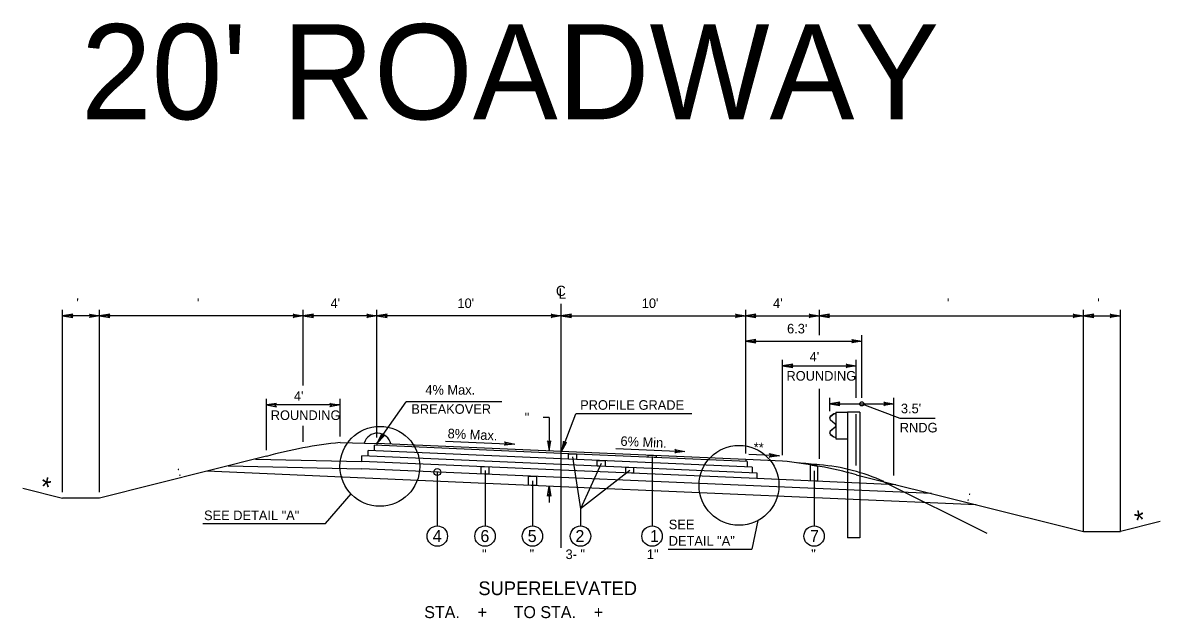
# Model space of a CAD drawing. Extents: x -540 to 1231, y -564 to 421.
# Drawn here: x 503.3 to 669.6, y -129.2 to -42.2 of the extents above; entities that cross this region are included whole.
import ezdxf

# ---------------------------------------------------------------- set-up
doc = ezdxf.new("R2010")
doc.units = 0
doc.layers.add('1', color=7, linetype='Continuous')
doc.layers.add('Des_ Drain_ Ftrs', color=7, linetype='Continuous')

msp = doc.modelspace()

# ---------------------------------------------------------------- linework, layer by layer
at = {"layer": '1'}
for p, q in [((509.17, -110.78), (509.17, -84.16)), ((514.55, -110.78), (514.55, -84.16)), ((544.33, -95.22), (544.33, -84.16)), ((555.1, -102.79), (555.1, -84.16)), ((582.04, -118.94), (582.04, -83.28)), ((608.98, -105.14), (608.98, -84.16)), ((619.76, -87.87), (619.76, -84.16)), ((658.35, -116.57), (658.35, -84.16)), ((663.74, -116.57), (663.74, -84.16)), ((514.55, -85.04), (509.17, -85.04)), ((544.33, -85.04), (514.55, -85.04)), ((555.1, -85.04), (544.33, -85.04)), ((582.04, -85.04), (555.1, -85.04)), ((582.04, -85.04), (608.98, -85.04)), ((608.98, -85.04), (619.76, -85.04)), ((619.76, -85.04), (658.35, -85.04)), ((658.35, -85.04), (663.74, -85.04)), ((625.95, -97.02), (625.95, -87.87)), ((608.98, -88.75), (625.95, -88.75)), ((614.37, -105.38), (614.37, -91.44)), ((614.37, -92.32), (625.15, -92.32)), ((625.15, -97.02), (625.15, -91.44)), ((619.76, -105.93), (619.76, -95.72)), ((538.94, -104.68), (538.94, -97.18)), ((549.71, -98.06), (538.94, -98.06)), ((549.71, -102.67), (549.71, -97.18)), ((555.1, -103.67), (559.38, -97.58)), ((573.33, -97.58), (559.38, -97.58)), ((621.26, -98.97), (621.26, -97.02)), ((621.26, -97.9), (630.65, -97.9)), ((625.95, -97.9), (631.51, -99.97)), ((630.65, -108.38), (630.65, -97.02)), ((582.05, -104.85), (584.17, -99.34)), ((601.09, -99.34), (584.17, -99.34)), ((621.86, -99.37), (621.34, -99.76)), ((621.87, -99.4), (621.36, -99.78)), ((622.17, -99.31), (621.86, -99.37)), ((622.17, -99.35), (621.87, -99.4)), ((622.17, -99.09), (622.17, -103.02)), ((622.17, -99.09), (623.86, -99.09)), ((623.86, -99.09), (623.86, -117.48)), ((625.68, -99.09), (623.86, -99.09)), ((625.15, -106.9), (625.15, -99.4)), ((625.68, -99.09), (625.68, -117.48)), ((544.33, -103.45), (544.33, -101.13)), ((580.26, -99.89), (579.38, -99.89)), ((580.26, -99.89), (580.26, -104.77)), ((621.33, -100.19), (622.06, -100.83)), ((622.06, -101.28), (621.33, -101.91)), ((621.35, -100.17), (622.08, -100.8)), ((622.08, -101.3), (621.35, -101.94)), ((622.14, -101.01), (622.14, -101.09)), ((622.17, -101.01), (622.17, -101.09)), ((631.51, -99.97), (636.67, -99.97)), ((621.34, -102.35), (621.86, -102.73)), ((621.36, -102.32), (621.87, -102.71)), ((621.86, -102.73), (622.17, -102.79)), ((621.87, -102.71), (622.17, -102.76)), ((622.17, -103.02), (623.86, -103.02)), ((549.71, -103.55), (555.1, -103.67)), ((582.04, -105.95), (553.83, -104.72)), ((553.83, -105.53), (553.83, -104.72)), ((582.04, -105.14), (554.76, -103.95)), ((554.76, -104.76), (554.76, -103.95)), ((582.04, -104.84), (555.1, -103.67)), ((555.1, -103.67), (555.1, -103.97)), ((565.12, -103.33), (575.23, -103.77)), ((589.99, -104.42), (600.11, -104.86)), ((538.94, -105.56), (514.55, -111.66)), ((537.34, -105.96), (552.91, -106.3)), ((582.04, -106.76), (552.91, -105.49)), ((552.91, -106.3), (552.91, -105.49)), ((552.91, -105.49), (552.91, -105.49)), ((582.04, -107.57), (552.91, -106.3)), ((608.99, -106.02), (582.04, -104.84)), ((609.22, -106.33), (582.04, -105.14)), ((609.93, -107.17), (582.04, -105.95)), ((583.68, -105.62), (584.84, -113.25)), ((595.3, -105.59), (595.3, -115.73)), ((614.37, -106.26), (608.99, -106.02)), ((608.99, -106.02), (608.99, -106.32)), ((609.22, -106.33), (609.22, -107.14)), ((613.93, -105.48), (609.43, -105.29)), ((582.04, -110), (530.24, -107.74)), ((533.37, -106.95), (552.91, -107.38)), ((582.04, -108.65), (552.91, -107.38)), ((563.92, -107.86), (563.92, -115.73)), ((570.89, -107.62), (570.89, -115.73)), ((610.63, -108.01), (582.04, -106.76)), ((610.63, -108.82), (582.04, -107.57)), ((587.85, -106.6), (584.84, -113.25)), ((592.03, -107.62), (584.84, -113.25)), ((609.93, -107.17), (609.93, -107.98)), ((610.63, -108.01), (610.63, -108.82)), ((610.64, -108.01), (610.63, -108.01)), ((618.98, -107.68), (618.98, -115.73)), ((621.26, -107.03), (621.26, -107.03)), ((577.82, -109.13), (577.82, -115.73)), ((608.99, -109.83), (582.04, -108.65)), ((630.9, -109.71), (610.63, -108.82)), ((625.15, -108.27), (658.35, -116.57)), ((629.15, -109.27), (644.2, -116.79)), ((503.34, -110.2), (509.17, -111.66)), ((547.57, -115.39), (551.31, -111.07)), ((580.26, -109.92), (580.26, -112.29)), ((642.67, -112.65), (582.04, -110)), ((636.13, -111.01), (608.99, -109.83)), ((514.55, -111.66), (509.17, -111.66)), ((584.84, -113.25), (584.84, -115.73)), ((529.64, -115.39), (547.57, -115.39)), ((610.78, -114.94), (609.89, -119.12)), ((669.56, -115.11), (663.74, -116.57)), ((625.68, -117.48), (623.86, -117.48)), ((658.35, -116.57), (663.74, -116.57)), ((597.66, -119.12), (609.89, -119.12))]:
    msp.add_line(p, q, dxfattribs=at)
for points in [[(583.11, -105.19), (584.25, -105.24), (584.25, -106.05), (583.11, -106)], [(587.28, -106.18), (588.43, -106.23), (588.43, -107.04), (587.28, -106.99)], [(594.73, -105.4), (595.88, -105.45), (595.88, -105.75), (594.73, -105.7)], [(570.31, -107.06), (571.46, -107.11), (571.46, -108.19), (570.31, -108.14)], [(591.46, -107.17), (592.6, -107.22), (592.6, -108.03), (591.46, -107.98)], [(618.46, -106.81), (619.5, -106.99), (619.5, -109.21), (618.46, -109.16)], [(577.25, -108.44), (578.39, -108.49), (578.39, -109.84), (577.25, -109.79)]]:
    msp.add_lwpolyline(points, close=True, dxfattribs=at)
for centre, radius in [((625.95, -97.9), 0.3), ((555.52, -107.03), 5.84), ((608.01, -109.8), 5.84), ((563.92, -107.86), 0.5), ((563.92, -117.22), 1.49), ((570.89, -117.22), 1.49), ((577.82, -117.22), 1.49), ((584.84, -117.22), 1.49), ((595.3, -117.22), 1.49), ((618.98, -117.22), 1.49)]:
    msp.add_circle(centre, radius, dxfattribs=at)
for centre, radius, start, end in [((621.51, -99.98), 0.278, 126.9799, 229.021), ((621.51, -99.98), 0.249, 126.9799, 229.021), ((621.9, -101.01), 0.249, 0, 49.0365), ((621.9, -101.09), 0.249, 310.9635, 0), ((621.9, -101.01), 0.278, 0, 49.0365), ((621.9, -101.09), 0.278, 310.9635, 0), ((555.17, -104.18), 2, 12.2852, 163.8849), ((621.51, -102.12), 0.278, 130.979, 233.0201), ((621.51, -102.12), 0.249, 130.979, 233.0201), ((556.61, -170.39), 67.19, 95.8901, 105.2487), ((607.49, -173.09), 67.19, 74.7593, 84.1179), ((608.94, -207.48), 101.24, 83.8633, 85.6775), ((617.64, -134.1), 27.37, 65.1374, 85.5513)]:
    msp.add_arc(centre, radius, start, end, dxfattribs=at)
at = {"layer": 'Des_ Drain_ Ftrs'}
for points in [[(509.17, -85.04), (510.65, -85.29), (510.36, -85.04), (510.65, -84.8)], [(514.55, -85.04), (513.07, -85.29), (513.36, -85.04), (513.07, -84.8)], [(514.55, -85.04), (516.04, -85.29), (515.75, -85.04), (516.04, -84.8)], [(544.33, -85.04), (542.84, -85.29), (543.13, -85.04), (542.84, -84.8)], [(544.33, -85.04), (545.81, -85.29), (545.52, -85.04), (545.81, -84.8)], [(555.1, -85.04), (553.61, -85.29), (553.91, -85.04), (553.61, -84.8)], [(555.1, -85.04), (556.59, -85.29), (556.3, -85.04), (556.59, -84.8)], [(582.04, -85.04), (580.55, -85.29), (580.85, -85.04), (580.55, -84.8)], [(582.04, -85.04), (583.53, -85.29), (583.24, -85.04), (583.53, -84.8)], [(608.98, -85.04), (607.5, -85.29), (607.79, -85.04), (607.5, -84.8)], [(608.98, -85.04), (610.47, -85.29), (610.18, -85.04), (610.47, -84.8)], [(619.76, -85.04), (618.27, -85.29), (618.57, -85.04), (618.27, -84.8)], [(619.76, -85.04), (621.25, -85.29), (620.95, -85.04), (621.25, -84.8)], [(658.35, -85.04), (656.86, -85.29), (657.15, -85.04), (656.86, -84.8)], [(658.35, -85.04), (659.84, -85.29), (659.54, -85.04), (659.84, -84.8)], [(663.74, -85.04), (662.25, -85.29), (662.54, -85.04), (662.25, -84.8)], [(608.98, -88.75), (610.47, -88.99), (610.17, -88.75), (610.47, -88.5)], [(625.95, -88.75), (624.47, -88.99), (624.76, -88.75), (624.47, -88.5)], [(614.37, -92.32), (615.86, -92.57), (615.57, -92.32), (615.86, -92.07)], [(625.15, -92.32), (623.66, -92.57), (623.96, -92.32), (623.66, -92.07)], [(538.94, -98.06), (540.43, -98.31), (540.13, -98.06), (540.43, -97.82)], [(549.71, -98.06), (548.23, -98.31), (548.52, -98.06), (548.23, -97.82)], [(621.26, -97.9), (622.75, -98.15), (622.45, -97.9), (622.75, -97.65)], [(630.65, -97.9), (629.16, -98.15), (629.45, -97.9), (629.16, -97.65)], [(555.1, -103.67), (556.15, -102.59), (555.78, -102.69), (555.75, -102.31)], [(575.23, -103.77), (573.74, -103.95), (574.04, -103.72), (573.76, -103.46)], [(580.26, -104.77), (580.51, -103.28), (580.26, -103.57), (580.02, -103.28)], [(582.05, -104.85), (582.82, -103.55), (582.48, -103.74), (582.35, -103.37)], [(600.11, -104.86), (598.61, -105.05), (598.91, -104.81), (598.63, -104.55)], [(613.93, -105.48), (612.43, -105.67), (612.73, -105.43), (612.45, -105.17)], [(580.26, -109.92), (580.51, -111.41), (580.26, -111.11), (580.02, -111.41)]]:
    msp.add_lwpolyline(points, close=True, dxfattribs=at)

# ---------------------------------------------------------------- texts
at = {"layer": '1'}
for s, height, p in [("20' ROADWAY", 13.8979, (511.85, -56.3)), (" '", 1.4, (510.66, -83.89)), ("  '", 1.4, (527.74, -83.89)), ("4'", 1.4, (548.32, -83.89)), ("10'", 1.4, (566.86, -83.89)), ("10'", 1.4, (593.8, -83.89)), ("4'", 1.4, (612.98, -83.89)), ("  '", 1.4, (637.36, -83.89)), (" '", 1.4, (659.85, -83.89)), ("6.3'", 1.4, (615.03, -87.6)), ("4'", 1.4, (618.33, -91.7)), ('ROUNDING', 1.4, (614.94, -94.5)), ("4'", 1.4, (542.97, -97.45)), ('4% Max.', 1.4, (562.17, -96.55)), ('BREAKOVER', 1.4, (560.12, -99.35)), ('PROFILE GRADE', 1.4, (584.79, -98.76)), ("3.5'", 1.4, (631.67, -99.27)), ('ROUNDING', 1.4, (539.58, -100.25)), ('RNDG', 1.4, (631.5, -102.07)), ('SEE DETAIL "A"', 1.4, (529.83, -114.89)), ('4', 1.75, (563.25, -118.09)), ('6', 1.75, (570.22, -118.09)), ('5', 1.75, (577.13, -118.09)), ('2', 1.75, (584.1, -118.09)), ('1', 1.75, (595, -118.09)), ('SEE', 1.4, (597.74, -116.22)), ('7', 1.75, (618.39, -118.09)), ('DETAIL "A"', 1.4, (597.74, -118.62)), (' "', 1.4, (569.94, -120.58)), (' "', 1.4, (576.88, -120.58)), ('3- "', 1.4, (582.66, -120.58)), ('1"', 1.4, (594.54, -120.58)), (' "', 1.4, (618.04, -120.58)), ('SUPERELEVATED', 2, (569.92, -125.85)), ('STA.    +      TO STA.    +     ', 1.75, (562.01, -129.21))]:
    msp.add_text(s, height=height, dxfattribs=at).set_placement(p)
for s, height, rotation, p in [('  "', 1.4, 0.1438, (575.65, -100.59)), ('8% Max.', 1.4, 357.3762, (565.4, -102.91)), ('6% Min.', 1.4, 357.3731, (590.66, -104.02)), ('**', 1.4, 357.2164, (610.11, -104.92)), (' : ', 1.4, 14.2282, (525.57, -108.62)), ('*', 2.8, 347.1521, (505.65, -111.22)), (' : ', 1.4, 345.7718, (640.7, -111.86)), ('*', 2.8, 12.8479, (666.2, -116.37))]:
    msp.add_text(s, height=height, rotation=rotation, dxfattribs=at).set_placement(p)
at = {"layer": 'Des_ Drain_ Ftrs'}
for s, p in [('C', (581.25, -82.13)), ('L', (581.64, -82.52))]:
    msp.add_text(s, height=1.5, dxfattribs=at).set_placement(p)

doc.saveas('drawing.dxf')
